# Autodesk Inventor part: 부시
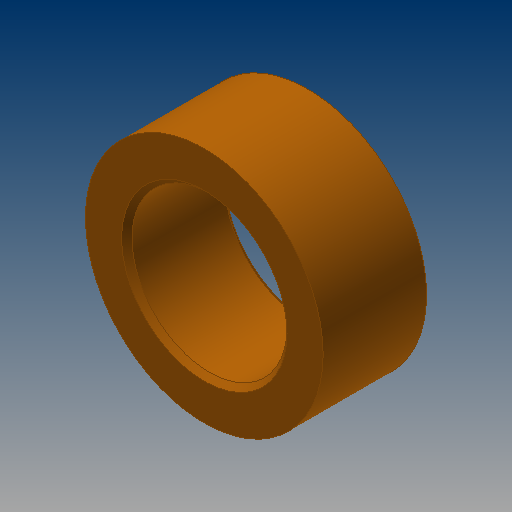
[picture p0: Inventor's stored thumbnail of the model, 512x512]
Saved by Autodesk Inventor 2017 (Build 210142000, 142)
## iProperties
Created: 2015-09
Part Number: 부시
Document SubType Name: Modeling
Designer: mduedu
Density: 1 g/cm^3
Material: 스테인리스강
Appearance: 주황색
Author: mduedu
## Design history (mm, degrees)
node "작업 평면1"
node "작업 평면2"
sketch "스케치1"
  geometry: C1 r 7.5 at (0, 0); C2 r 11.5 at (0, 0); 1 further point
  constraints: 2 centre point, 2 coincident
  dimensions: "d0" = 15 diameter of C1; "d1" = 23 diameter of C2
extrude "돌출1" new body sketch "스케치1" stored distance "d2" = 9.85; taper "d3" = 0 deg
chamfer "모따기1" distance "d4" = 0.5; stored, may be unused: second distance "d5" = 2, angle "d6" = 45 deg
node "솔리드1"
